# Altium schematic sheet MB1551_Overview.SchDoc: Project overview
size A4; Date: Not used; ApprovedBy: Not used; CheckedBy: Not used; Author: Not used; CompanyName: STMicroelectronics; DrawnBy: Not used; Engineer: Not used; Organization: Not used; Address1: Not used; Address2: Not used; Address3: Not used; Address4: Not used; DocumentNumber: 1; Revision: Not used; SheetNumber: 1; SheetTotal: 16
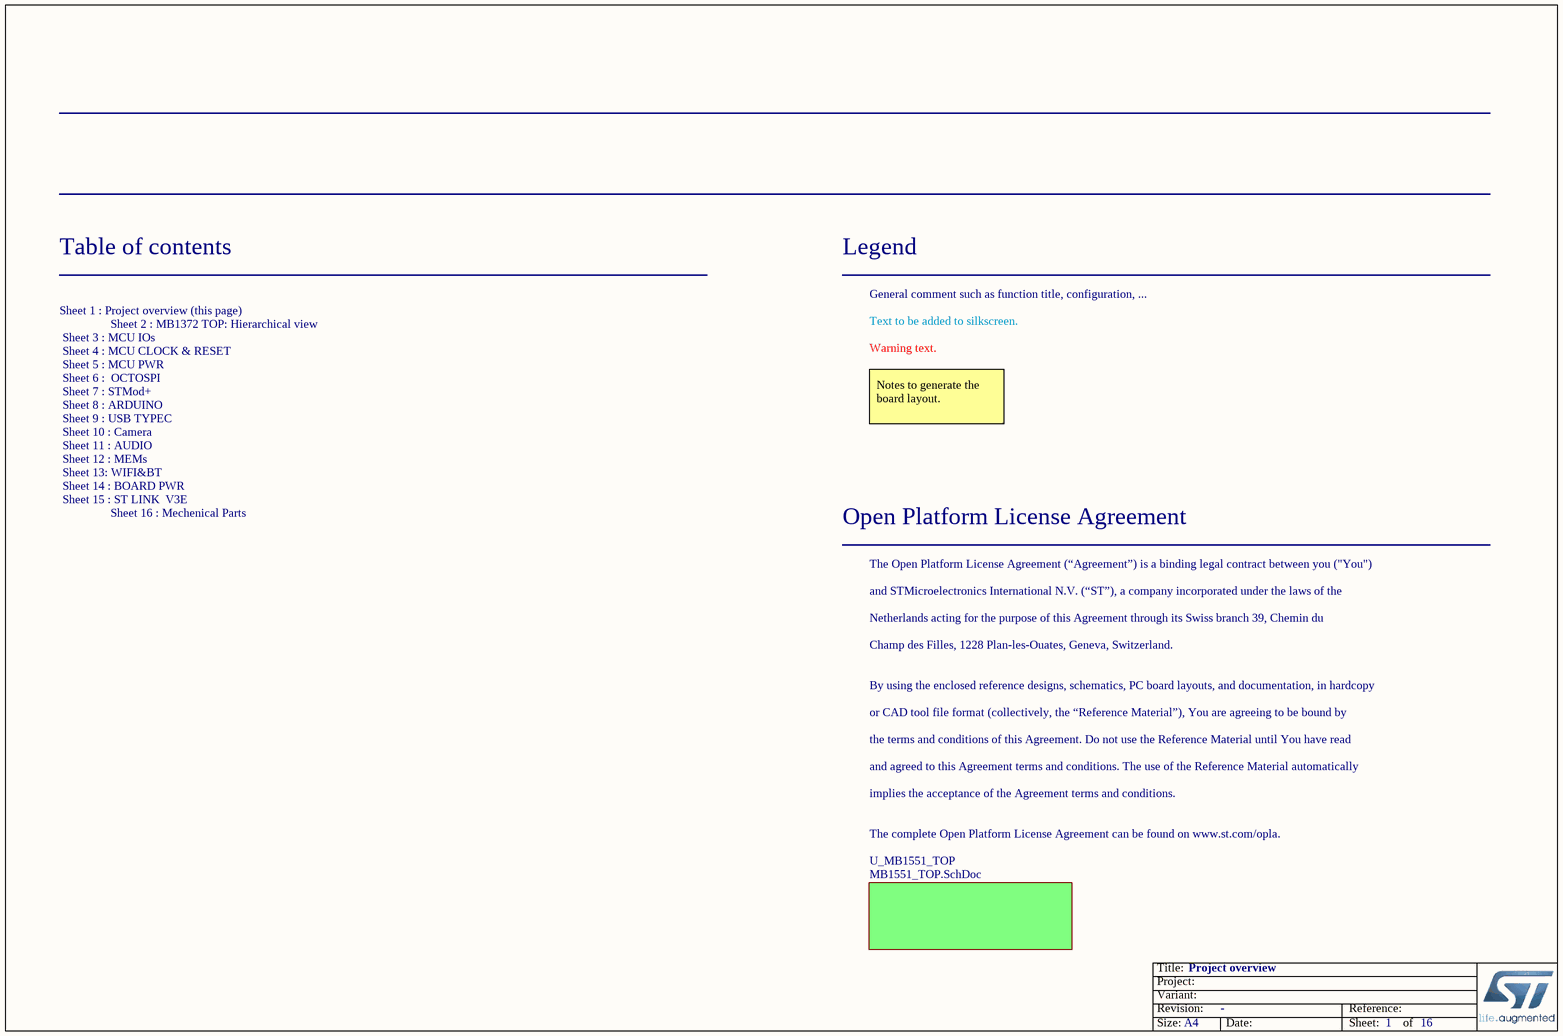
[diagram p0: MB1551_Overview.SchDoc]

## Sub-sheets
U_MB1551_TOP = MB1551_TOP.SchDoc: no entries

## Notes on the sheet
- Table of contents
- Legend
- General comment such as function title, configuration, ...
- Text to be added to silkscreen.
- Warning text.
- Notes to generate the board layout.
- Open Platform License Agreement
- The Open Platform License Agreement (“Agreement”) is a binding legal contract between you ("You")
- Sheet 1 : Project overview (this page)
  Sheet 2 : MB1372 TOP: Hierarchical view
  Sheet 3 : MCU IOs
  Sheet 4 : MCU CLOCK & RESET
  Sheet 5 : MCU PWR
  Sheet 6 :  OCTOSPI
  Sheet 7 : STMod+
  Sheet 8 : ARDUINO
  Sheet 9 : USB TYPEC
  Sheet 10 : Camera
  Sheet 11 : AUDIO
  Sheet 12 : MEMs
  Sheet 13: WIFI&BT
  Sheet 14 : BOARD PWR
  Sheet 15 : ST LINK  V3E
  Sheet 16 : Mechenical Parts
- and STMicroelectronics International N.V. (“ST”), a company incorporated under the laws of the
- Netherlands acting for the purpose of this Agreement through its Swiss branch 39, Chemin du
- Champ des Filles, 1228 Plan-les-Ouates, Geneva, Switzerland.
- By using the enclosed reference designs, schematics, PC board layouts, and documentation, in hardcopy
- or CAD tool file format (collectively, the “Reference Material”), You are agreeing to be bound by
- the terms and conditions of this Agreement. Do not use the Reference Material until You have read
- and agreed to this Agreement terms and conditions. The use of the Reference Material automatically
- implies the acceptance of the Agreement terms and conditions.
- The complete Open Platform License Agreement can be found on www.st.com/opla.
